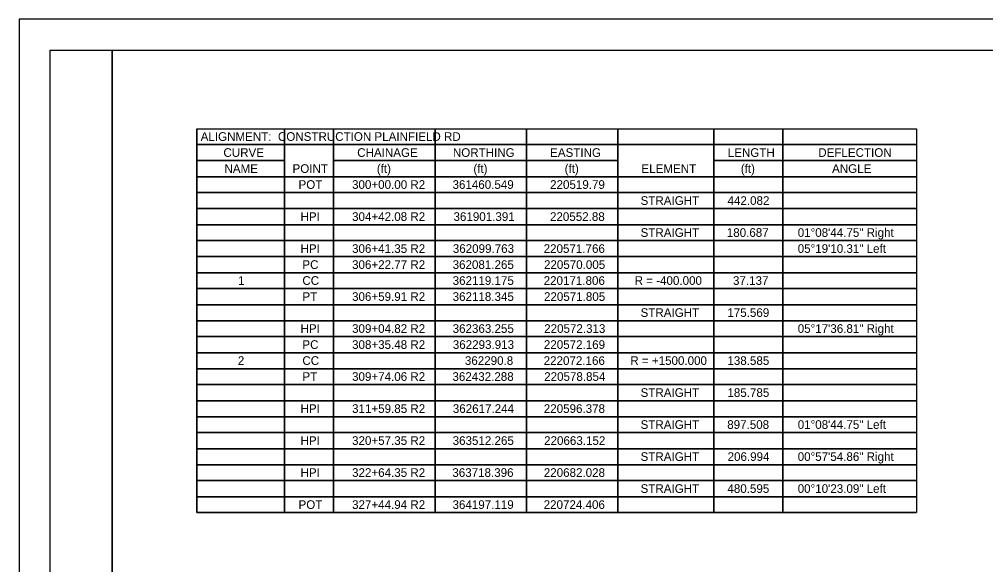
# Model space of a CAD drawing. Extents: x 1.1 to 35.1, y 0 to 27.2.
# Drawn here: x 1.1 to 16.71, y 13.18 to 22 of the extents above; entities that cross this region are included whole.
import ezdxf

# ---------------------------------------------------------------- set-up
doc = ezdxf.new("R2010")
doc.units = 0
for name, color, linetype in [('RW_X_CL_100_Bearings', 7, 'Continuous'), ('SH_Border', 7, 'Continuous'), ('SH_Cut_Line', 7, 'Continuous')]:
    doc.layers.add(name, color=color, linetype=linetype)

msp = doc.modelspace()

# ---------------------------------------------------------------- linework, layer by layer
at = {"layer": 'RW_X_CL_100_Bearings'}
for p, q in [((3.969, 20.232), (15.593, 20.232)), ((3.969, 20.232), (3.969, 19.974)), ((15.593, 20.232), (15.593, 19.974)), ((3.969, 19.974), (15.593, 19.974)), ((3.969, 19.974), (3.969, 14.025)), ((5.384, 19.974), (5.384, 14.025)), ((6.175, 19.974), (6.175, 14.025)), ((7.818, 19.974), (7.818, 14.025)), ((9.294, 19.974), (9.294, 14.025)), ((10.77, 19.974), (10.77, 14.025)), ((12.322, 19.974), (12.322, 14.025)), ((13.433, 19.974), (13.433, 14.025)), ((15.593, 19.974), (15.593, 14.025)), ((3.969, 19.456), (15.593, 19.456)), ((3.969, 19.198), (15.593, 19.198)), ((3.969, 18.939), (15.593, 18.939)), ((3.969, 18.68), (15.593, 18.68)), ((3.969, 18.422), (15.593, 18.422)), ((3.969, 18.163), (15.593, 18.163)), ((3.969, 17.904), (15.593, 17.904)), ((3.969, 17.646), (15.593, 17.646)), ((3.969, 17.387), (15.593, 17.387)), ((3.969, 17.128), (15.593, 17.128)), ((3.969, 16.87), (15.593, 16.87)), ((3.969, 16.611), (15.593, 16.611)), ((3.969, 16.352), (15.593, 16.352)), ((3.969, 16.094), (15.593, 16.094)), ((3.969, 15.835), (15.593, 15.835)), ((3.969, 15.576), (15.593, 15.576)), ((3.969, 15.318), (15.593, 15.318)), ((3.969, 15.059), (15.593, 15.059)), ((3.969, 14.8), (15.593, 14.8)), ((3.969, 14.542), (15.593, 14.542)), ((3.969, 14.283), (15.593, 14.283)), ((3.969, 14.025), (15.593, 14.025))]:
    msp.add_line(p, q, dxfattribs=at)
for points in [[(3.969, 20.232), (5.384, 20.232), (5.384, 19.974), (3.969, 19.974)], [(5.384, 20.232), (6.175, 20.232), (6.175, 19.974), (5.384, 19.974)], [(6.175, 20.232), (7.818, 20.232), (7.818, 19.974), (6.175, 19.974)], [(7.818, 20.232), (9.294, 20.232), (9.294, 19.974), (7.818, 19.974)], [(9.294, 20.232), (10.77, 20.232), (10.77, 19.974), (9.294, 19.974)], [(10.77, 20.232), (12.322, 20.232), (12.322, 19.974), (10.77, 19.974)], [(12.322, 20.232), (13.433, 20.232), (13.433, 19.974), (12.322, 19.974)], [(13.433, 20.232), (15.593, 20.232), (15.593, 19.974), (13.433, 19.974)], [(3.969, 19.974), (5.384, 19.974), (5.384, 19.715), (3.969, 19.715)], [(5.384, 19.974), (6.175, 19.974), (6.175, 19.456), (5.384, 19.456)], [(6.175, 19.974), (7.818, 19.974), (7.818, 19.715), (6.175, 19.715)], [(7.818, 19.974), (9.294, 19.974), (9.294, 19.715), (7.818, 19.715)], [(9.294, 19.974), (10.77, 19.974), (10.77, 19.715), (9.294, 19.715)], [(10.77, 19.974), (12.322, 19.974), (12.322, 19.456), (10.77, 19.456)], [(12.322, 19.974), (13.433, 19.974), (13.433, 19.715), (12.322, 19.715)], [(13.433, 19.974), (15.593, 19.974), (15.593, 19.715), (13.433, 19.715)], [(3.969, 19.715), (5.384, 19.715), (5.384, 19.456), (3.969, 19.456)], [(6.175, 19.715), (7.818, 19.715), (7.818, 19.456), (6.175, 19.456)], [(7.818, 19.715), (9.294, 19.715), (9.294, 19.456), (7.818, 19.456)], [(9.294, 19.715), (10.77, 19.715), (10.77, 19.456), (9.294, 19.456)], [(12.322, 19.715), (13.433, 19.715), (13.433, 19.456), (12.322, 19.456)], [(13.433, 19.715), (15.593, 19.715), (15.593, 19.456), (13.433, 19.456)], [(3.969, 19.456), (5.384, 19.456), (5.384, 19.198), (3.969, 19.198)], [(5.384, 19.456), (6.175, 19.456), (6.175, 19.198), (5.384, 19.198)], [(6.175, 19.456), (7.818, 19.456), (7.818, 19.198), (6.175, 19.198)], [(7.818, 19.456), (9.294, 19.456), (9.294, 19.198), (7.818, 19.198)], [(9.294, 19.456), (10.77, 19.456), (10.77, 19.198), (9.294, 19.198)], [(10.77, 19.456), (12.322, 19.456), (12.322, 19.198), (10.77, 19.198)], [(12.322, 19.456), (13.433, 19.456), (13.433, 19.198), (12.322, 19.198)], [(13.433, 19.456), (15.593, 19.456), (15.593, 19.198), (13.433, 19.198)], [(3.969, 19.198), (5.384, 19.198), (5.384, 18.939), (3.969, 18.939)], [(5.384, 19.198), (6.175, 19.198), (6.175, 18.939), (5.384, 18.939)], [(6.175, 19.198), (7.818, 19.198), (7.818, 18.939), (6.175, 18.939)], [(7.818, 19.198), (9.294, 19.198), (9.294, 18.939), (7.818, 18.939)], [(9.294, 19.198), (10.77, 19.198), (10.77, 18.939), (9.294, 18.939)], [(10.77, 19.198), (12.322, 19.198), (12.322, 18.939), (10.77, 18.939)], [(12.322, 19.198), (13.433, 19.198), (13.433, 18.939), (12.322, 18.939)], [(13.433, 19.198), (15.593, 19.198), (15.593, 18.939), (13.433, 18.939)], [(3.969, 18.939), (5.384, 18.939), (5.384, 18.68), (3.969, 18.68)], [(5.384, 18.939), (6.175, 18.939), (6.175, 18.68), (5.384, 18.68)], [(6.175, 18.939), (7.818, 18.939), (7.818, 18.68), (6.175, 18.68)], [(7.818, 18.939), (9.294, 18.939), (9.294, 18.68), (7.818, 18.68)], [(9.294, 18.939), (10.77, 18.939), (10.77, 18.68), (9.294, 18.68)], [(10.77, 18.939), (12.322, 18.939), (12.322, 18.68), (10.77, 18.68)], [(12.322, 18.939), (13.433, 18.939), (13.433, 18.68), (12.322, 18.68)], [(13.433, 18.939), (15.593, 18.939), (15.593, 18.68), (13.433, 18.68)], [(3.969, 18.68), (5.384, 18.68), (5.384, 18.422), (3.969, 18.422)], [(5.384, 18.68), (6.175, 18.68), (6.175, 18.422), (5.384, 18.422)], [(6.175, 18.68), (7.818, 18.68), (7.818, 18.422), (6.175, 18.422)], [(7.818, 18.68), (9.294, 18.68), (9.294, 18.422), (7.818, 18.422)], [(9.294, 18.68), (10.77, 18.68), (10.77, 18.422), (9.294, 18.422)], [(10.77, 18.68), (12.322, 18.68), (12.322, 18.422), (10.77, 18.422)], [(12.322, 18.68), (13.433, 18.68), (13.433, 18.422), (12.322, 18.422)], [(13.433, 18.68), (15.593, 18.68), (15.593, 18.422), (13.433, 18.422)], [(3.969, 18.422), (5.384, 18.422), (5.384, 18.163), (3.969, 18.163)], [(5.384, 18.422), (6.175, 18.422), (6.175, 18.163), (5.384, 18.163)], [(6.175, 18.422), (7.818, 18.422), (7.818, 18.163), (6.175, 18.163)], [(7.818, 18.422), (9.294, 18.422), (9.294, 18.163), (7.818, 18.163)], [(9.294, 18.422), (10.77, 18.422), (10.77, 18.163), (9.294, 18.163)], [(10.77, 18.422), (12.322, 18.422), (12.322, 18.163), (10.77, 18.163)], [(12.322, 18.422), (13.433, 18.422), (13.433, 18.163), (12.322, 18.163)], [(13.433, 18.422), (15.593, 18.422), (15.593, 18.163), (13.433, 18.163)], [(3.969, 18.163), (5.384, 18.163), (5.384, 17.904), (3.969, 17.904)], [(5.384, 18.163), (6.175, 18.163), (6.175, 17.904), (5.384, 17.904)], [(6.175, 18.163), (7.818, 18.163), (7.818, 17.904), (6.175, 17.904)], [(7.818, 18.163), (9.294, 18.163), (9.294, 17.904), (7.818, 17.904)], [(9.294, 18.163), (10.77, 18.163), (10.77, 17.904), (9.294, 17.904)], [(10.77, 18.163), (12.322, 18.163), (12.322, 17.904), (10.77, 17.904)], [(12.322, 18.163), (13.433, 18.163), (13.433, 17.904), (12.322, 17.904)], [(13.433, 18.163), (15.593, 18.163), (15.593, 17.904), (13.433, 17.904)], [(3.969, 17.904), (5.384, 17.904), (5.384, 17.646), (3.969, 17.646)], [(5.384, 17.904), (6.175, 17.904), (6.175, 17.646), (5.384, 17.646)], [(6.175, 17.904), (7.818, 17.904), (7.818, 17.646), (6.175, 17.646)], [(7.818, 17.904), (9.294, 17.904), (9.294, 17.646), (7.818, 17.646)], [(9.294, 17.904), (10.77, 17.904), (10.77, 17.646), (9.294, 17.646)], [(10.77, 17.904), (12.322, 17.904), (12.322, 17.646), (10.77, 17.646)], [(12.322, 17.904), (13.433, 17.904), (13.433, 17.646), (12.322, 17.646)], [(13.433, 17.904), (15.593, 17.904), (15.593, 17.646), (13.433, 17.646)], [(3.969, 17.646), (5.384, 17.646), (5.384, 17.387), (3.969, 17.387)], [(5.384, 17.646), (6.175, 17.646), (6.175, 17.387), (5.384, 17.387)], [(6.175, 17.646), (7.818, 17.646), (7.818, 17.387), (6.175, 17.387)], [(7.818, 17.646), (9.294, 17.646), (9.294, 17.387), (7.818, 17.387)], [(9.294, 17.646), (10.77, 17.646), (10.77, 17.387), (9.294, 17.387)], [(10.77, 17.646), (12.322, 17.646), (12.322, 17.387), (10.77, 17.387)], [(12.322, 17.646), (13.433, 17.646), (13.433, 17.387), (12.322, 17.387)], [(13.433, 17.646), (15.593, 17.646), (15.593, 17.387), (13.433, 17.387)], [(3.969, 17.387), (5.384, 17.387), (5.384, 17.128), (3.969, 17.128)], [(5.384, 17.387), (6.175, 17.387), (6.175, 17.128), (5.384, 17.128)], [(6.175, 17.387), (7.818, 17.387), (7.818, 17.128), (6.175, 17.128)], [(7.818, 17.387), (9.294, 17.387), (9.294, 17.128), (7.818, 17.128)], [(9.294, 17.387), (10.77, 17.387), (10.77, 17.128), (9.294, 17.128)], [(10.77, 17.387), (12.322, 17.387), (12.322, 17.128), (10.77, 17.128)], [(12.322, 17.387), (13.433, 17.387), (13.433, 17.128), (12.322, 17.128)], [(13.433, 17.387), (15.593, 17.387), (15.593, 17.128), (13.433, 17.128)], [(3.969, 17.128), (5.384, 17.128), (5.384, 16.87), (3.969, 16.87)], [(5.384, 17.128), (6.175, 17.128), (6.175, 16.87), (5.384, 16.87)], [(6.175, 17.128), (7.818, 17.128), (7.818, 16.87), (6.175, 16.87)], [(7.818, 17.128), (9.294, 17.128), (9.294, 16.87), (7.818, 16.87)], [(9.294, 17.128), (10.77, 17.128), (10.77, 16.87), (9.294, 16.87)], [(10.77, 17.128), (12.322, 17.128), (12.322, 16.87), (10.77, 16.87)], [(12.322, 17.128), (13.433, 17.128), (13.433, 16.87), (12.322, 16.87)], [(13.433, 17.128), (15.593, 17.128), (15.593, 16.87), (13.433, 16.87)], [(3.969, 16.87), (5.384, 16.87), (5.384, 16.611), (3.969, 16.611)], [(5.384, 16.87), (6.175, 16.87), (6.175, 16.611), (5.384, 16.611)], [(6.175, 16.87), (7.818, 16.87), (7.818, 16.611), (6.175, 16.611)], [(7.818, 16.87), (9.294, 16.87), (9.294, 16.611), (7.818, 16.611)], [(9.294, 16.87), (10.77, 16.87), (10.77, 16.611), (9.294, 16.611)], [(10.77, 16.87), (12.322, 16.87), (12.322, 16.611), (10.77, 16.611)], [(12.322, 16.87), (13.433, 16.87), (13.433, 16.611), (12.322, 16.611)], [(13.433, 16.87), (15.593, 16.87), (15.593, 16.611), (13.433, 16.611)], [(3.969, 16.611), (5.384, 16.611), (5.384, 16.352), (3.969, 16.352)], [(5.384, 16.611), (6.175, 16.611), (6.175, 16.352), (5.384, 16.352)], [(6.175, 16.611), (7.818, 16.611), (7.818, 16.352), (6.175, 16.352)], [(7.818, 16.611), (9.294, 16.611), (9.294, 16.352), (7.818, 16.352)], [(9.294, 16.611), (10.77, 16.611), (10.77, 16.352), (9.294, 16.352)], [(10.77, 16.611), (12.322, 16.611), (12.322, 16.352), (10.77, 16.352)], [(12.322, 16.611), (13.433, 16.611), (13.433, 16.352), (12.322, 16.352)], [(13.433, 16.611), (15.593, 16.611), (15.593, 16.352), (13.433, 16.352)], [(3.969, 16.352), (5.384, 16.352), (5.384, 16.094), (3.969, 16.094)], [(5.384, 16.352), (6.175, 16.352), (6.175, 16.094), (5.384, 16.094)], [(6.175, 16.352), (7.818, 16.352), (7.818, 16.094), (6.175, 16.094)], [(7.818, 16.352), (9.294, 16.352), (9.294, 16.094), (7.818, 16.094)], [(9.294, 16.352), (10.77, 16.352), (10.77, 16.094), (9.294, 16.094)], [(10.77, 16.352), (12.322, 16.352), (12.322, 16.094), (10.77, 16.094)], [(12.322, 16.352), (13.433, 16.352), (13.433, 16.094), (12.322, 16.094)], [(13.433, 16.352), (15.593, 16.352), (15.593, 16.094), (13.433, 16.094)], [(3.969, 16.094), (5.384, 16.094), (5.384, 15.835), (3.969, 15.835)], [(5.384, 16.094), (6.175, 16.094), (6.175, 15.835), (5.384, 15.835)], [(6.175, 16.094), (7.818, 16.094), (7.818, 15.835), (6.175, 15.835)], [(7.818, 16.094), (9.294, 16.094), (9.294, 15.835), (7.818, 15.835)], [(9.294, 16.094), (10.77, 16.094), (10.77, 15.835), (9.294, 15.835)], [(10.77, 16.094), (12.322, 16.094), (12.322, 15.835), (10.77, 15.835)], [(12.322, 16.094), (13.433, 16.094), (13.433, 15.835), (12.322, 15.835)], [(13.433, 16.094), (15.593, 16.094), (15.593, 15.835), (13.433, 15.835)], [(3.969, 15.835), (5.384, 15.835), (5.384, 15.576), (3.969, 15.576)], [(5.384, 15.835), (6.175, 15.835), (6.175, 15.576), (5.384, 15.576)], [(6.175, 15.835), (7.818, 15.835), (7.818, 15.576), (6.175, 15.576)], [(7.818, 15.835), (9.294, 15.835), (9.294, 15.576), (7.818, 15.576)], [(9.294, 15.835), (10.77, 15.835), (10.77, 15.576), (9.294, 15.576)], [(10.77, 15.835), (12.322, 15.835), (12.322, 15.576), (10.77, 15.576)], [(12.322, 15.835), (13.433, 15.835), (13.433, 15.576), (12.322, 15.576)], [(13.433, 15.835), (15.593, 15.835), (15.593, 15.576), (13.433, 15.576)], [(3.969, 15.576), (5.384, 15.576), (5.384, 15.318), (3.969, 15.318)], [(5.384, 15.576), (6.175, 15.576), (6.175, 15.318), (5.384, 15.318)], [(6.175, 15.576), (7.818, 15.576), (7.818, 15.318), (6.175, 15.318)], [(7.818, 15.576), (9.294, 15.576), (9.294, 15.318), (7.818, 15.318)], [(9.294, 15.576), (10.77, 15.576), (10.77, 15.318), (9.294, 15.318)], [(10.77, 15.576), (12.322, 15.576), (12.322, 15.318), (10.77, 15.318)], [(12.322, 15.576), (13.433, 15.576), (13.433, 15.318), (12.322, 15.318)], [(13.433, 15.576), (15.593, 15.576), (15.593, 15.318), (13.433, 15.318)], [(3.969, 15.318), (5.384, 15.318), (5.384, 15.059), (3.969, 15.059)], [(5.384, 15.318), (6.175, 15.318), (6.175, 15.059), (5.384, 15.059)], [(6.175, 15.318), (7.818, 15.318), (7.818, 15.059), (6.175, 15.059)], [(7.818, 15.318), (9.294, 15.318), (9.294, 15.059), (7.818, 15.059)], [(9.294, 15.318), (10.77, 15.318), (10.77, 15.059), (9.294, 15.059)], [(10.77, 15.318), (12.322, 15.318), (12.322, 15.059), (10.77, 15.059)], [(12.322, 15.318), (13.433, 15.318), (13.433, 15.059), (12.322, 15.059)], [(13.433, 15.318), (15.593, 15.318), (15.593, 15.059), (13.433, 15.059)], [(3.969, 15.059), (5.384, 15.059), (5.384, 14.8), (3.969, 14.8)], [(5.384, 15.059), (6.175, 15.059), (6.175, 14.8), (5.384, 14.8)], [(6.175, 15.059), (7.818, 15.059), (7.818, 14.8), (6.175, 14.8)], [(7.818, 15.059), (9.294, 15.059), (9.294, 14.8), (7.818, 14.8)], [(9.294, 15.059), (10.77, 15.059), (10.77, 14.8), (9.294, 14.8)], [(10.77, 15.059), (12.322, 15.059), (12.322, 14.8), (10.77, 14.8)], [(12.322, 15.059), (13.433, 15.059), (13.433, 14.8), (12.322, 14.8)], [(13.433, 15.059), (15.593, 15.059), (15.593, 14.8), (13.433, 14.8)], [(3.969, 14.8), (5.384, 14.8), (5.384, 14.542), (3.969, 14.542)], [(5.384, 14.8), (6.175, 14.8), (6.175, 14.542), (5.384, 14.542)], [(6.175, 14.8), (7.818, 14.8), (7.818, 14.542), (6.175, 14.542)], [(7.818, 14.8), (9.294, 14.8), (9.294, 14.542), (7.818, 14.542)], [(9.294, 14.8), (10.77, 14.8), (10.77, 14.542), (9.294, 14.542)], [(10.77, 14.8), (12.322, 14.8), (12.322, 14.542), (10.77, 14.542)], [(12.322, 14.8), (13.433, 14.8), (13.433, 14.542), (12.322, 14.542)], [(13.433, 14.8), (15.593, 14.8), (15.593, 14.542), (13.433, 14.542)], [(3.969, 14.542), (5.384, 14.542), (5.384, 14.283), (3.969, 14.283)], [(5.384, 14.542), (6.175, 14.542), (6.175, 14.283), (5.384, 14.283)], [(6.175, 14.542), (7.818, 14.542), (7.818, 14.283), (6.175, 14.283)], [(7.818, 14.542), (9.294, 14.542), (9.294, 14.283), (7.818, 14.283)], [(9.294, 14.542), (10.77, 14.542), (10.77, 14.283), (9.294, 14.283)], [(10.77, 14.542), (12.322, 14.542), (12.322, 14.283), (10.77, 14.283)], [(12.322, 14.542), (13.433, 14.542), (13.433, 14.283), (12.322, 14.283)], [(13.433, 14.542), (15.593, 14.542), (15.593, 14.283), (13.433, 14.283)], [(3.969, 14.283), (5.384, 14.283), (5.384, 14.025), (3.969, 14.025)], [(5.384, 14.283), (6.175, 14.283), (6.175, 14.025), (5.384, 14.025)], [(6.175, 14.283), (7.818, 14.283), (7.818, 14.025), (6.175, 14.025)], [(7.818, 14.283), (9.294, 14.283), (9.294, 14.025), (7.818, 14.025)], [(9.294, 14.283), (10.77, 14.283), (10.77, 14.025), (9.294, 14.025)], [(10.77, 14.283), (12.322, 14.283), (12.322, 14.025), (10.77, 14.025)], [(12.322, 14.283), (13.433, 14.283), (13.433, 14.025), (12.322, 14.025)], [(13.433, 14.283), (15.593, 14.283), (15.593, 14.025), (13.433, 14.025)]]:
    msp.add_lwpolyline(points, close=True, dxfattribs=at)
at = {"layer": 'SH_Border'}
for points in [[(1.598, 21.5), (2.598, 21.5), (2.598, 0.5), (1.598, 0.5)], [(2.598, 21.5), (34.598, 21.5), (34.598, 0.5), (2.598, 0.5)]]:
    msp.add_lwpolyline(points, close=True, dxfattribs=at)
at = {"layer": 'SH_Cut_Line'}
msp.add_lwpolyline([(1.098, 0), (35.098, 0), (35.098, 22), (1.098, 22)], close=True, dxfattribs=at)

# ---------------------------------------------------------------- texts
at = {"layer": 'RW_X_CL_100_Bearings'}
for s, height, p in [('ALIGNMENT:  CONSTRUCTION PLAINFIELD RD', 0.13998, (4.029, 20.035)), ('CURVE', 0.14, (4.396, 19.776)), ('CHAINAGE', 0.14, (6.558, 19.776)), ('NORTHING', 0.14, (8.104, 19.776)), ('EASTING', 0.14, (9.675, 19.776)), ('LENGTH', 0.14, (12.546, 19.776)), ('DEFLECTION', 0.14, (14.008, 19.776)), ('NAME', 0.14, (4.413, 19.517)), ('POINT', 0.14, (5.513, 19.517)), ('(ft)', 0.14, (6.875, 19.517)), ('(ft)', 0.14, (8.435, 19.517)), ('(ft)', 0.14, (9.91, 19.517)), ('ELEMENT', 0.14, (11.151, 19.517)), ('(ft)', 0.14, (12.756, 19.517)), ('ANGLE', 0.14, (14.231, 19.517)), ('POT', 0.14, (5.61, 19.259)), ('300+00.00 R2', 0.13998, (6.475, 19.259)), ('361460.549', 0.14, (8.098, 19.259)), ('220519.79', 0.14, (9.675, 19.259)), ('STRAIGHT', 0.14, (11.137, 19)), ('442.082', 0.14, (12.542, 19)), ('HPI', 0.14, (5.642, 18.741)), ('304+42.08 R2', 0.13998, (6.475, 18.741)), ('361901.391', 0.14, (8.114, 18.741)), ('220552.88', 0.14, (9.673, 18.741)), ('STRAIGHT', 0.14, (11.137, 18.483)), ('180.687', 0.14, (12.53, 18.483)), ('01°08\'44.75" Right', 0.13998, (13.676, 18.483)), ('HPI', 0.14, (5.642, 18.224)), ('306+41.35 R2', 0.13998, (6.475, 18.224)), ('362099.763', 0.14, (8.103, 18.224)), ('220571.766', 0.14, (9.571, 18.224)), ('05°19\'10.31" Left', 0.13998, (13.676, 18.224)), ('PC', 0.14, (5.672, 17.965)), ('306+22.77 R2', 0.13998, (6.475, 17.965)), ('362081.265', 0.14, (8.1, 17.965)), ('220570.005', 0.14, (9.576, 17.965)), ('1', 0.14, (4.635, 17.707)), ('CC', 0.14, (5.672, 17.707)), ('362119.175', 0.14, (8.1, 17.707)), ('220171.806', 0.14, (9.571, 17.707)), ('R = -400.000', 0.13998, (11.041, 17.707)), ('37.137', 0.14, (12.63, 17.707)), ('PT', 0.14, (5.673, 17.448)), ('306+59.91 R2', 0.13998, (6.475, 17.448)), ('362118.345', 0.14, (8.1, 17.448)), ('220571.805', 0.14, (9.576, 17.448)), ('STRAIGHT', 0.14, (11.137, 17.189)), ('175.569', 0.14, (12.539, 17.189)), ('HPI', 0.14, (5.642, 16.931)), ('309+04.82 R2', 0.13998, (6.475, 16.931)), ('362363.255', 0.14, (8.1, 16.931)), ('220572.313', 0.14, (9.579, 16.931)), ('05°17\'36.81" Right', 0.13998, (13.676, 16.931)), ('PC', 0.14, (5.672, 16.672)), ('308+35.48 R2', 0.13998, (6.475, 16.672)), ('362293.913', 0.14, (8.103, 16.672)), ('220572.169', 0.14, (9.574, 16.672)), ('2', 0.14, (4.629, 16.413)), ('CC', 0.14, (5.672, 16.413)), ('362290.8', 0.14, (8.298, 16.413)), ('222072.166', 0.14, (9.571, 16.413)), ('R = +1500.000', 0.13998, (10.971, 16.413)), ('138.585', 0.14, (12.54, 16.413)), ('PT', 0.14, (5.673, 16.155)), ('309+74.06 R2', 0.13998, (6.475, 16.155)), ('362432.288', 0.14, (8.097, 16.155)), ('220578.854', 0.14, (9.579, 16.155)), ('STRAIGHT', 0.14, (11.137, 15.896)), ('185.785', 0.14, (12.54, 15.896)), ('HPI', 0.14, (5.642, 15.637)), ('311+59.85 R2', 0.13998, (6.475, 15.637)), ('362617.244', 0.14, (8.103, 15.637)), ('220596.378', 0.14, (9.573, 15.637)), ('STRAIGHT', 0.14, (11.137, 15.379)), ('897.508', 0.14, (12.537, 15.379)), ('01°08\'44.75" Left', 0.13998, (13.676, 15.379)), ('HPI', 0.14, (5.642, 15.12)), ('320+57.35 R2', 0.13998, (6.475, 15.12)), ('363512.265', 0.14, (8.1, 15.12)), ('220663.152', 0.14, (9.578, 15.12)), ('STRAIGHT', 0.14, (11.137, 14.861)), ('206.994', 0.14, (12.543, 14.861)), ('00°57\'54.86" Right', 0.13998, (13.676, 14.861)), ('HPI', 0.14, (5.642, 14.603)), ('322+64.35 R2', 0.13998, (6.475, 14.603)), ('363718.396', 0.14, (8.095, 14.603)), ('220682.028', 0.14, (9.573, 14.603)), ('STRAIGHT', 0.14, (11.137, 14.344)), ('480.595', 0.14, (12.54, 14.344)), ('00°10\'23.09" Left', 0.13998, (13.676, 14.344)), ('POT', 0.14, (5.61, 14.085)), ('327+44.94 R2', 0.13998, (6.475, 14.085)), ('364197.119', 0.14, (8.098, 14.085)), ('220724.406', 0.14, (9.571, 14.085))]:
    msp.add_text(s, height=height, dxfattribs=at).set_placement(p)

doc.saveas('drawing.dxf')
